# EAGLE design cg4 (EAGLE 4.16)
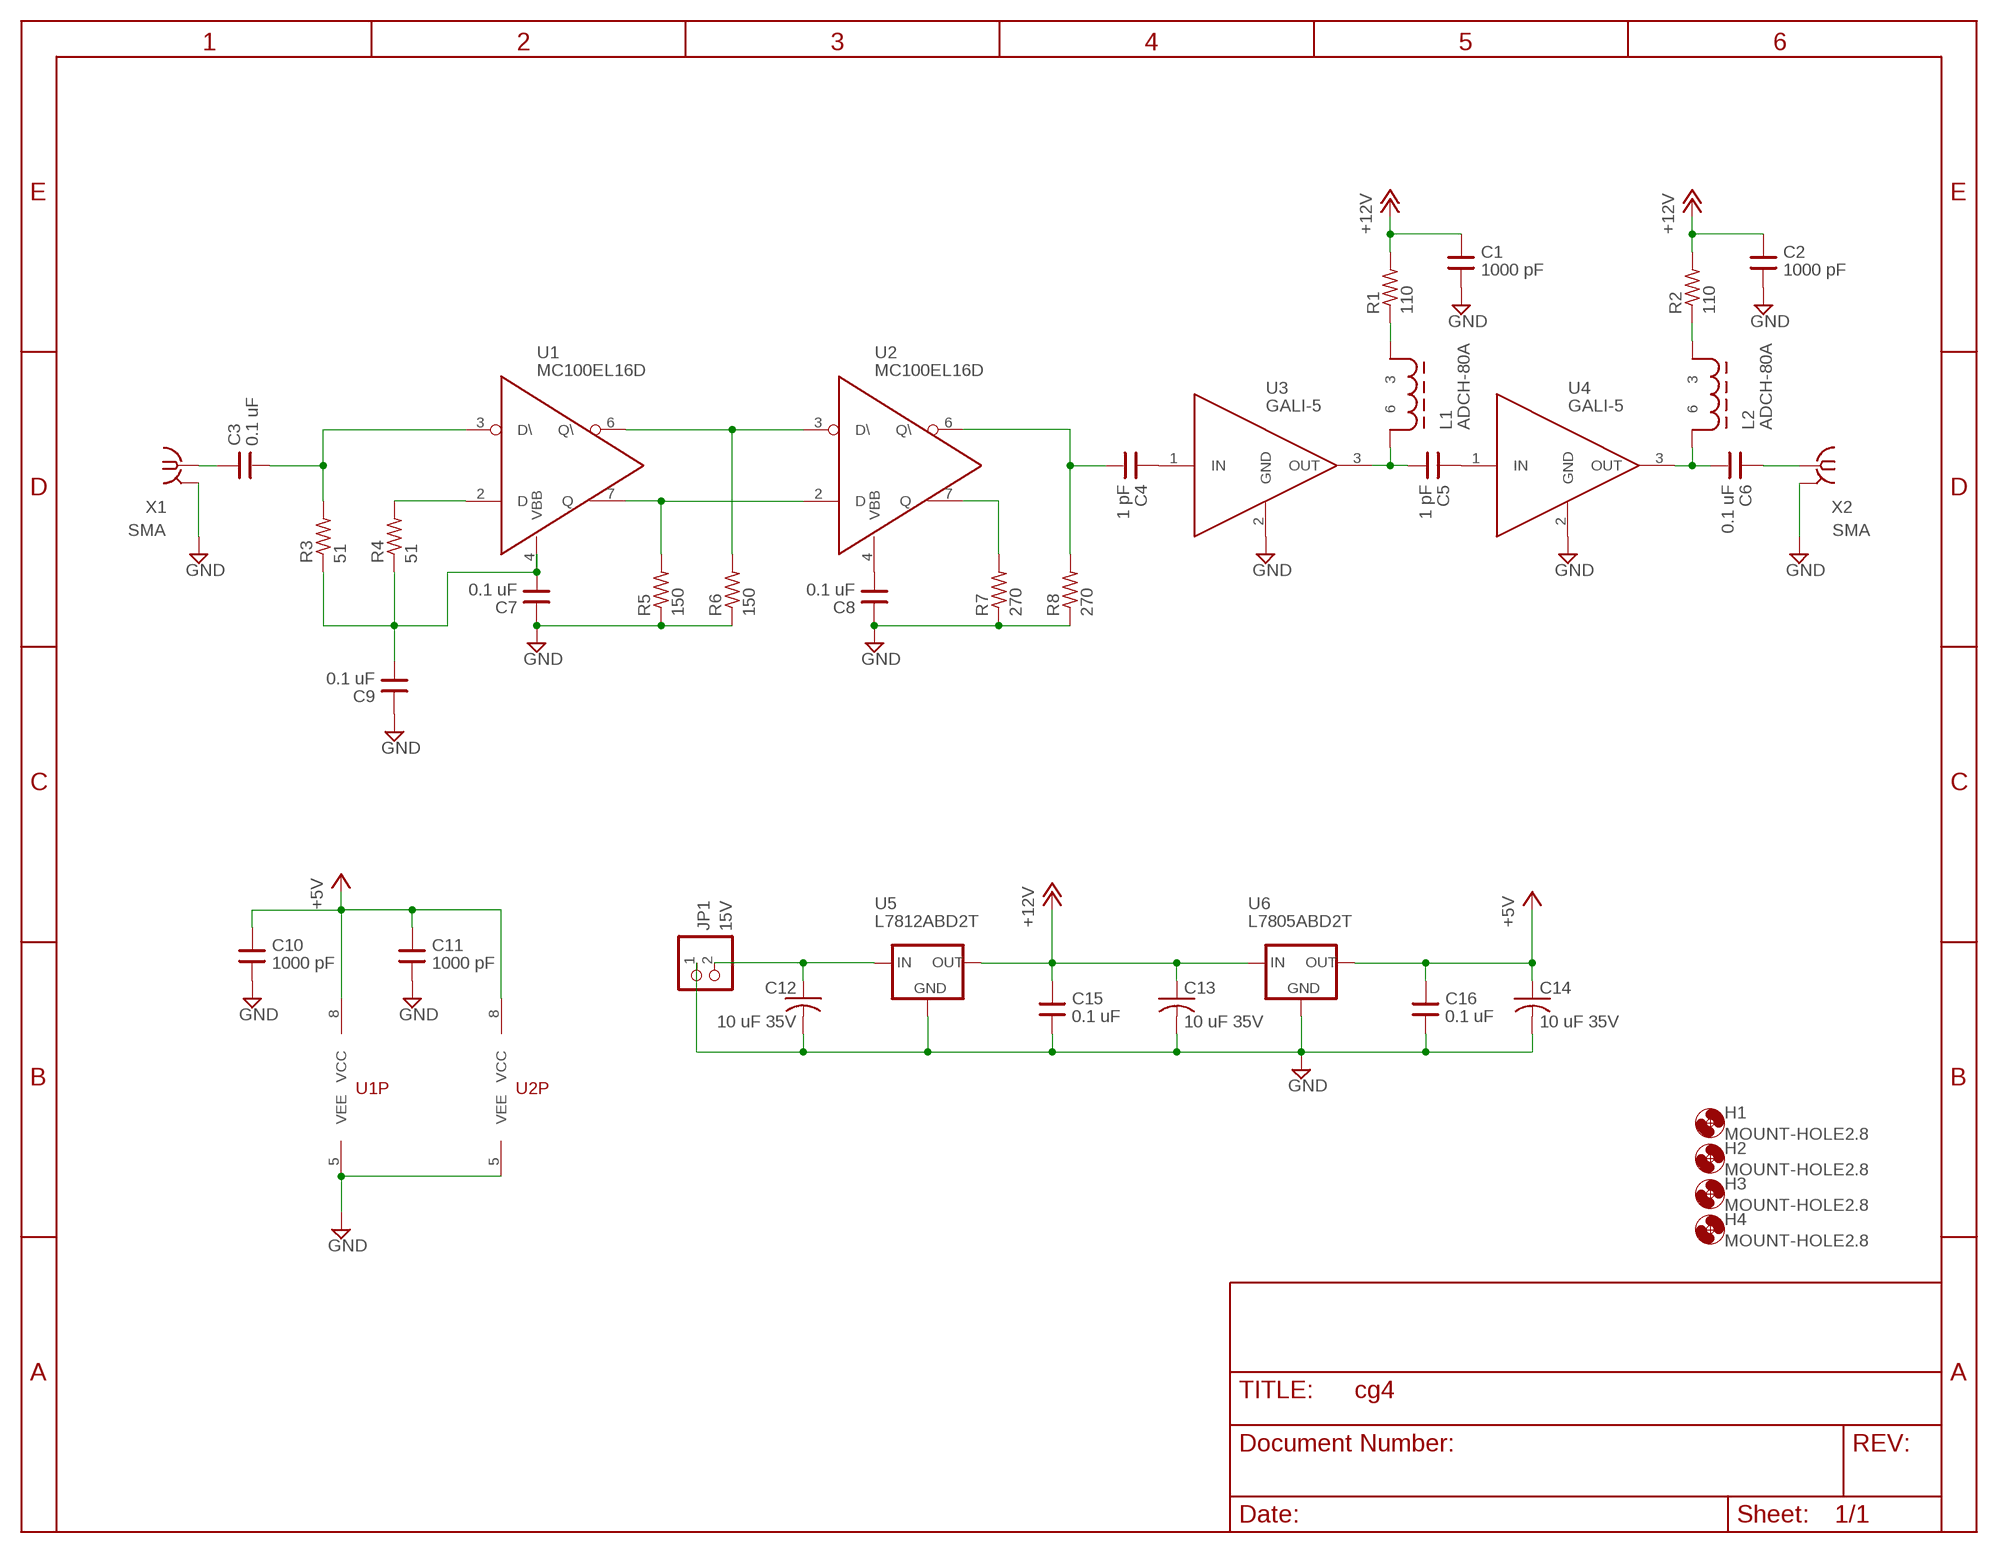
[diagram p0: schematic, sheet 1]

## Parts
C1  1000 pF  C1206  [C1206]
C2  1000 pF  C1206  [C1206]
C3  0.1 uF  C1206  [C1206]
C4  1 pF  C1206  [C1206]
C5  1 pF  C1206  [C1206]
C6  0.1 uF  C1206  [C1206]
C7  0.1 uF  C1206  [C1206]
C8  0.1 uF  C1206  [C1206]
C9  0.1 uF  C1206  [C1206]
C10  1000 pF  C1206  [C1206]
C11  1000 pF  C1206  [C1206]
C12  10 uF 35V  AVX_TAJ_CAP  [SMC-D]
C13  10 uF 35V  AVX_TAJ_CAP  [SMC-D]
C14  10 uF 35V  AVX_TAJ_CAP  [SMC-D]
C15  0.1 uF  C1206  [C1206]
C16  0.1 uF  C1206  [C1206]
H1  MOUNT-HOLE2.8  [2,8]
H2  MOUNT-HOLE2.8  [2,8]
H3  MOUNT-HOLE2.8  [2,8]
H4  MOUNT-HOLE2.8  [2,8]
JP1  15V  PINHD-1X2  [1X02]
L1  ADCH-80A  ADCH  [CD542]
L2  ADCH-80A  ADCH  [CD542]
R1  110  R-US_R2512  [R2512]
R2  110  R-US_R2512  [R2512]
R3  51  R-US_R1206  [R1206]
R4  51  R-US_R1206  [R1206]
R5  150  R-US_R1206  [R1206]
R6  150  R-US_R1206  [R1206]
R7  270  R-US_R1206  [R1206]
R8  270  R-US_R1206  [R1206]
U1  MC100EL16D  [SOIC8]
U2  MC100EL16D  [SOIC8]
U3  GALI-5  GALI  [DF782]
U4  GALI-5  GALI  [DF782]
U5  L7812ABD2T  L78XXABD2T  [D2PACK]
U6  L7805ABD2T  L78XXABD2T  [D2PACK]
X1  SMA  BU-SMA-V  [BU-SMA-V]
X2  SMA  BU-SMA-V  [BU-SMA-V]

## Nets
+5V: C10.1 C11.1 C14.+ C16.1 U1.8(VCC) U2.8(VCC) U6.3(OUT)
+12V: C1.1 C2.1 C13.+ C15.1 R1.2 R2.2 U5.3(OUT) U6.1(IN)
GND: C1.2 C2.2 C7.1 C8.1 C9.1 C10.2 C11.2 C12.- C13.- C14.- C15.2 C16.2 JP1.1 R5.1 R6.1 R7.1 R8.1 U1.5(VEE) U2.5(VEE) U3.2(GND) U4.2(GND) U5.2(GND) U6.2(GND) X1.2(GND) X2.2(GND)
N$1: C3.2 R3.2 U1.3(D\)
N$2: C4.2 R8.2 U2.6(Q\)
N$3: R4.2 U1.2(D)
N$4: C4.1 U3.1(IN)
N$5: C12.+ JP1.2 U5.1(IN)
N$6: C5.1 U4.1(IN)
N$7: R5.2 U1.7(Q) U2.2(D)
N$8: C5.2 L1.6 U3.3(OUT)
N$9: L1.3 R1.1
N$10: R6.2 U1.6(Q\) U2.3(D\)
N$11: R7.2 U2.7(Q)
N$12: C8.2 U2.4(VBB)
N$13: L2.3 R2.1
N$14: C6.2 L2.6 U4.3(OUT)
N$15: C3.1 X1.1
N$16: C6.1 X2.1
N$17: C7.2 C9.2 R3.1 R4.1 U1.4(VBB)

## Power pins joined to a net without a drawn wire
GND: U3.TAB(GND) U4.TAB(GND) X1.3(GND) X1.4(GND) X1.5(GND) X2.3(GND) X2.4(GND) X2.5(GND)

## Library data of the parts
C1-C11 C15 C16 = KE5FX:C1206
C12-C14 = KE5FX:AVX_TAJ_CAP
H1-H4 = holes:MOUNT-HOLE: MOUNTING HOLE with drill center marker
JP1 = pinhead:PINHD-1X2: PIN HEADER
L1 L2 = KE5FX:ADCH*
R1-R8 = rcl:R-US_: RESISTOR, American symbol
U1 U2 = KE5FX:MC100EL16D
U3 U4 = KE5FX:GALI*
U5 U6 = KE5FX:L78XXABD2T
X1 X2 = con-coax:BU-SMA-V: FEMALE SMA CONNECTOR Radiall distributor RS 112-3794

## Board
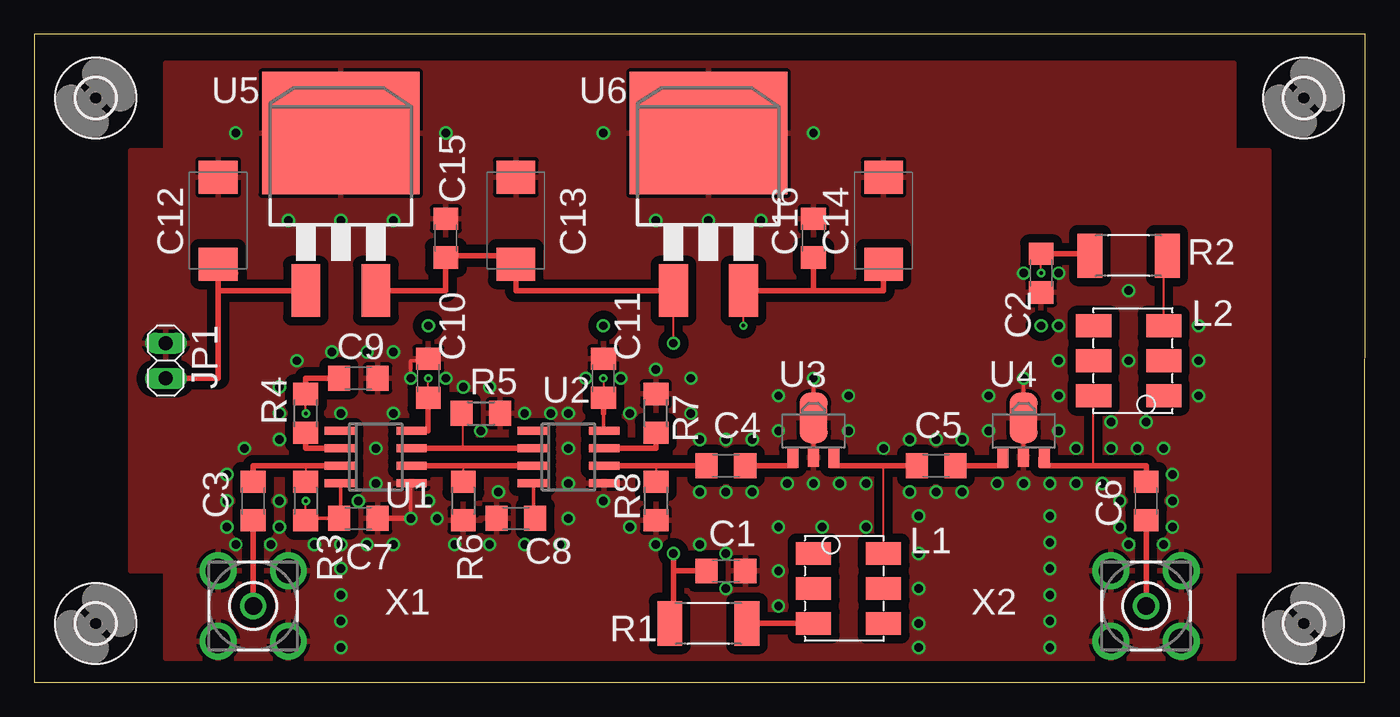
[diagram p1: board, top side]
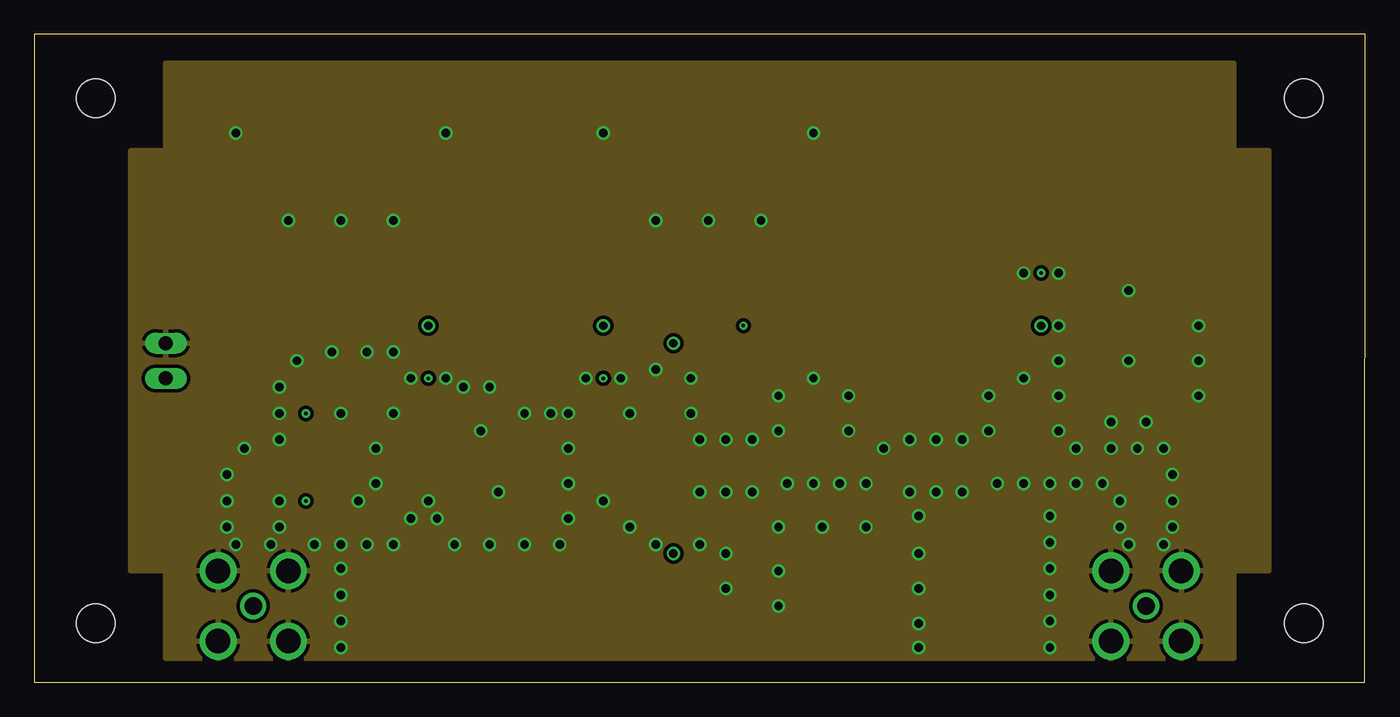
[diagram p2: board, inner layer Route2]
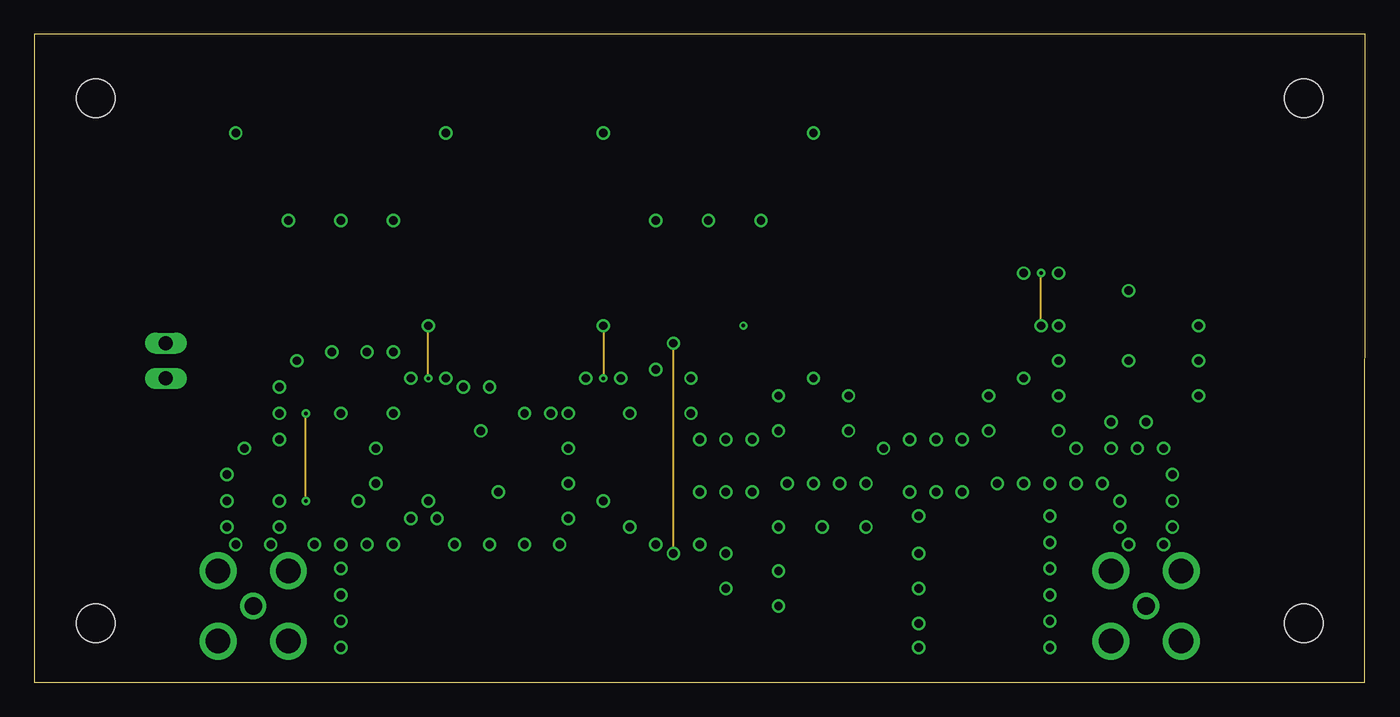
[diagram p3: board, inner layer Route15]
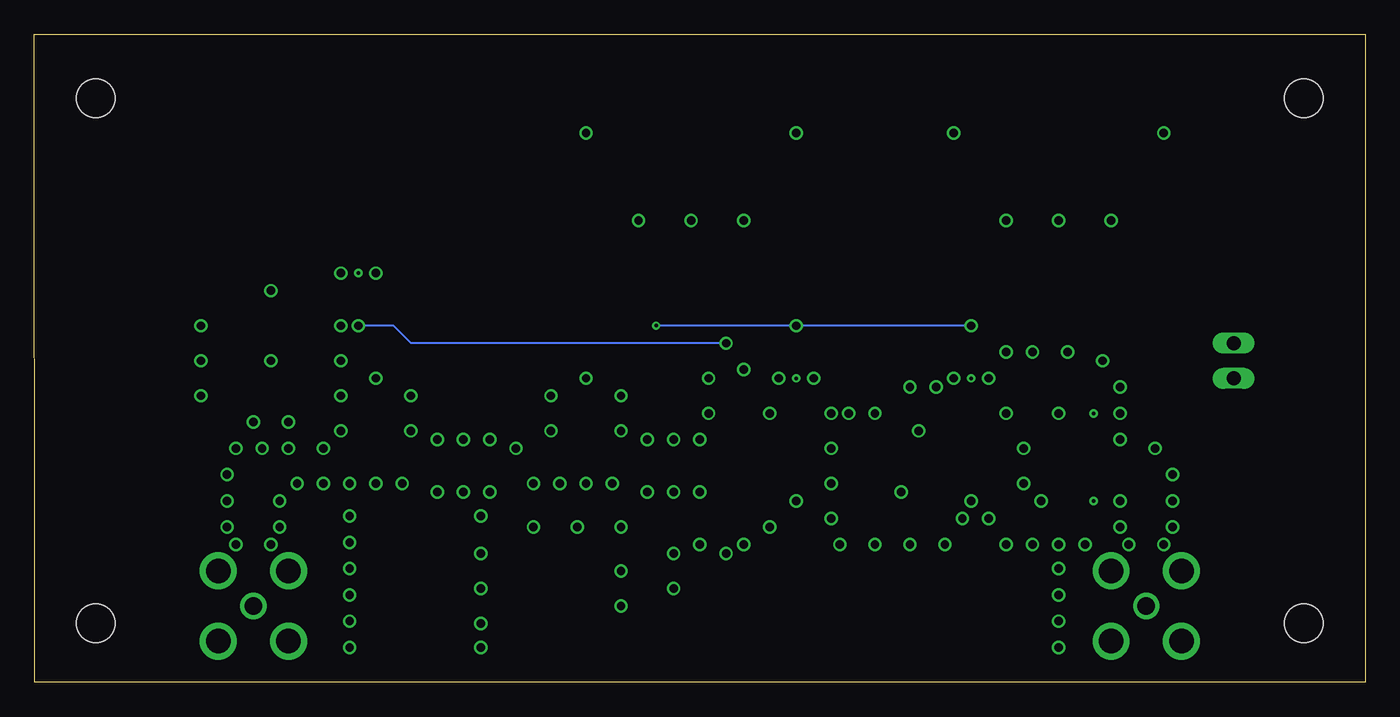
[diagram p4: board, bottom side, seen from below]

Size 96.52 x 46.99 mm. Coordinates in mm from the lower left corner, seen from the top.
Outline: 0,0 96.5,0 96.52,46.99 0,46.99 0,0
Copper layers (1+2*15+16): Top 0.035mm / dielectric 0.226mm / Route2 0.035mm / dielectric 1mm / Route15 0.035mm / dielectric 0.221mm / Bottom 0.035mm
Design rules "4pcb_4layer_8mm_clearance": minimum track width 5mil, minimum drill 0.2mm, track to track 8mil, track to pad 6mil, pad to pad 8mil, via to via 8mil, smd to smd 8mil, copper to edge 20mil, drill to drill 12mil, minimum pad ring 8mil, minimum via ring 7mil, stop-mask expansion 0mil, vias tented up to drill 0.3mm, thermal gap 10mil

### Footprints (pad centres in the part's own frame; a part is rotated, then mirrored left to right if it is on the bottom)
C1206 = smd 1.6 x 1.8: 1 -1.4,0; 2 1.4,0
SMC-D = smd 2.4 x 2.8: + -3.15,0; - 3.15,0
2,8 = hole 2.8: 0,0
1X02 = drill 1.016 long: 1 -1.27,0; 2 1.27,0
CD542 = smd 1.651 x 2.54: 1 -2.54,-2.54; 2 0,-2.54; 3 2.54,-2.54; 4 2.54,2.54; 5 0,2.54; 6 -2.54,2.54
R2512 = smd 1.8 x 3.2: 1 -2.8,0; 2 2.8,0
R1206 = smd 1.6 x 1.8: 1 -1.4,0; 2 1.4,0
SOIC8 = smd 0.6 x 2.2: 1 1.27,-0.06; 2 2.54,-0.06; 3 3.81,-0.06; 4 5.08,-0.06; 5 5.08,5.14; 6 3.81,5.14; 7 2.54,5.14; 8 1.27,5.14
DF782 = smd 0.8 x 1.4: 1 -1.499,-1.981; 2 0,-1.905; 3 1.499,-1.981 | smd 2.032 x 3.65: TAB 0,0.94
D2PACK = smd 2.083 x 3.81: 1 -2.54,-8.89; 3 2.54,-8.89 | smd 11.43 x 8.89: 2 0,2.54
BU-SMA-V = drill 1.27 round: 1 0,0 | drill 1.778 round: 2 -2.55,2.55; 3 2.55,2.55; 4 2.55,-2.55; 5 -2.55,-2.55

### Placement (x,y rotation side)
C1  50.16,8.09 0 top
C2  73.02,29.68 270 top
C3  15.87,13.17 90 top
C4  50.16,15.71 180 top
C5  65.4,15.71 180 top
C6  80.64,13.17 90 top
C7  23.49,11.9 180 top
C8  34.92,11.9 0 top
C9  23.49,22.06 180 top
C10  28.57,22.06 90 top
C11  41.27,22.06 90 top
C12  13.33,33.49 90 top
C13  34.92,33.49 90 top
C14  61.59,33.49 90 top
C15  29.84,32.22 90 top
C16  56.51,32.22 90 top
H1  92.07,42.38 0 top
H2  92.07,4.28 0 top
H3  4.44,4.28 0 top
H4  4.44,42.38 0 top
JP1  9.52,23.33 270 top
L1  59.05,6.82 270 top
L2  79.37,23.33 90 top
R1  48.89,4.28 180 top
R2  79.37,30.95 180 top
R3  19.68,13.17 90 top
R4  19.68,19.52 270 top
R5  32.38,19.52 180 top
R6  31.11,13.17 90 top
R7  45.08,19.52 270 top
R8  45.08,13.17 90 top
U1  22.22,19.52 270 top
U2  36.19,19.52 270 top
U3  56.51,18.25 0 top
U4  71.75,18.25 0 top
U5  22.22,37.3 0 top
U6  48.89,37.3 0 top
X1  15.87,5.55 0 top
X2  80.64,5.55 0 top

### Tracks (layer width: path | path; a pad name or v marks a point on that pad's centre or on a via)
+5V  (via drill 0.25 pad 0.41, 0.61 pad 0.97)
  Top 0.127: v41.27,22.06 C11.1 | 28.57,20.79 v28.57,22.06 | v51.43,25.87 U6.3
  Top 0.254: 41.27,19.52 41.27,18.25 U2.8
  Top 0.406: C11.1 41.27,19.52 | 27.3,18.25 U1.8 28.57,18.25 C10.1 28.57,20.79 | U6.3 56.51,28.41 | 56.51,30.95 C16.1 56.51,28.41 | 56.51,28.41 61.59,28.41 C14.+ 61.59,30.95
  Route15 0.127: v41.27,25.87 v41.27,22.06 | v28.57,22.06 v28.57,25.87
  Bottom 0.127: v51.43,25.87 v41.27,25.87 v28.57,25.87
+12V  (via drill 0.25 pad 0.41, 0.61, 0.61 pad 0.97)
  Top 0.127: R2.2 76.83,30.95 76.83,31.08 | v46.35,24.6 U6.1 | R1.2 46.35,5.55 | C13.+ 33.65,30.95 | v73.02,29.68 C2.1 | 48.89,8.09 C1.1
  Top 0.381: C2.1 76.83,31.08 | 46.35,5.55 46.35,8.09 | 46.35,8.09 v46.35,9.36 | 46.35,8.09 48.89,8.09
  Top 0.406: R1.2 46.35,4.28 | 45.08,28.41 U6.1 34.92,28.41 C13.+ 34.92,30.95 33.65,30.95 29.84,30.95 C15.1 29.84,28.41 U5.3
  Route15 0.127: v46.35,9.36 v46.35,24.6 | v73.02,25.87 v73.02,29.68
  Bottom 0.127: v46.35,24.6 69.21,24.6 70.48,25.87 v73.02,25.87
GND  (via drill 0.61, 0.61 pad 0.97)
  Top 0.254: C7.1 24.76,11.9 | R7.1 45.08,20.79 | v27.3,11.9 27.3,14.44 U1.5 | v56.51,22.06 U3.TAB U3.2 | v71.75,22.06 U4.TAB U4.2 | C11.2 41.27,23.33 | C9.1 24.76,22.06 | v27.3,22.06 27.3,23.33 28.57,23.33 C10.2
  Top 0.406: 24.76,11.9 v27.3,11.9 | C1.2 51.43,8.09
  other vias: 45.08,22.7 52.7,33.49 35.55,19.52 71.75,14.44 75.56,16.98 69.21,20.79 74.29,20.79 56.51,14.44 59.05,18.25 53.97,20.79 59.05,20.79 53.97,18.25 69.21,18.25 74.29,18.25 65.4,17.61 63.49,17.61 50.16,17.61 48.25,17.61 78.1,18.88 78.1,16.98 75.56,14.44 73.66,14.44 69.84,14.44 67.3,13.8 65.4,13.8 63.49,13.8 60.32,14.44 48.25,9.99 60.32,11.27 48.25,13.8 54.6,14.44 58.41,14.44 74.29,23.33 74.29,25.87 84.45,25.87 84.45,23.33 84.45,20.79 79.37,23.33 64.13,9.36 64.13,6.82 64.13,4.28 53.97,8.09 53.97,5.55 28.57,13.17 26.03,19.52 17.77,17.61 15.23,16.98 17.77,19.52 17.77,21.43 19.05,23.33 21.59,23.96 24.12,23.96 26.03,23.96 17.77,11.27 20.32,9.99 24.12,9.99 26.03,9.99 29.21,11.9 29.84,22.06 37.46,19.52 47.62,22.06 14.6,39.84 29.84,39.84 41.27,39.84 56.51,39.84 18.41,33.49 45.08,33.49 22.22,33.49 48.89,33.49 38.73,16.98 38.73,14.44 38.73,11.9 43.17,11.27 57.14,11.27 33.01,9.99 30.48,9.99 38.09,9.99 45.08,9.99 31.11,21.43 24.76,16.98 24.76,14.44 22.22,19.52 23.49,13.17 38.73,19.52 33.01,21.43 32.38,18.25 43.17,19.52 33.65,13.8 41.27,13.17 50.16,9.36 26.03,33.49 40,22.06 42.54,22.06 71.75,29.68 74.29,29.68 50.16,6.82 17.77,13.17 17.14,9.99 14.6,9.99 13.96,11.27 13.96,13.17 22.22,9.99 13.96,15.07 35.55,9.99 47.62,19.52 77.47,14.44 78.73,13.17 82.55,13.17 82.55,11.27 81.91,9.99 79.37,9.99 78.73,11.27 82.55,15.07 81.91,16.98 80.64,18.88 80,16.98 67.3,17.61 61.59,16.98 52.06,17.61 52.06,13.8 50.16,13.8 53.97,11.27 79.37,28.41 22.22,2.54 22.22,4.45 22.22,6.35 22.22,8.26 73.66,2.54 73.66,4.45 73.66,6.35 73.66,8.26 73.66,10.16 73.66,12.07 64.13,12.07 64.13,2.54
  pour Route2 (isolate 0.254): 6.98,38.57 6.98,8.09 9.52,8.09 9.52,1.74 86.99,1.74 86.99,8.09 89.53,8.09 89.53,38.57 86.99,38.57 86.99,44.92 9.52,44.92 9.52,38.57
  pour Top (isolate 0.61): 6.98,38.57 6.98,8.09 9.52,8.09 9.52,1.74 86.99,1.74 86.99,8.09 89.53,8.09 89.53,38.57 86.99,38.57 86.99,44.92 9.52,44.92 9.52,38.57
N$1
  Top 0.127: U1.3 20.95,15.71 19.68,15.71 R3.2
  Top 0.381: 20.95,15.71 15.87,15.71 C3.2
  Top 0.406: U1.3 22.22,15.71 | C3.2 15.87,14.44
N$2
  Top 0.127: 45.08,15.71 R8.2
  Top 0.254: 42.54,15.71 U2.6 41.27,15.71
  Top 0.381: C4.2 45.08,15.71 42.54,15.71
  Top 0.406: R8.2 45.08,14.44 | C4.2 48.89,15.71
N$3
  Top 0.381: 19.68,16.98 U1.2
  Top 0.406: U1.2 22.22,16.98 | 19.68,18.25 R4.2 19.68,16.98
N$4
  Top 0.127: 55.24,15.71 U3.1
  Top 0.381: C4.1 55.24,15.71
N$5
  Top 0.127: C12.+ 12.06,29.68
  Top 0.254: C12.+ 14.6,29.68
  Top 0.406: JP1.2 13.33,22.06 13.33,28.41 | 13.33,28.41 C12.+ 13.33,30.95 | 14.6,29.68 13.33,29.68 13.33,28.41 | 13.33,28.41 U5.1
N$6
  Top 0.254: C5.1 66.67,15.71 | 70.48,15.71 U4.1
  Top 0.381: C5.1 70.48,15.71
N$7
  Top 0.127: 31.11,16.98 31.11,19.52
  Top 0.254: U1.7 27.3,16.98
  Top 0.305: 31.11,19.52 R5.2
  Top 0.381: U1.7 31.11,16.98 36.19,16.98
  Top 0.406: 36.19,16.98 U2.2
N$8
  Top 0.127: L1.6 61.59,15.71
  Top 0.254: 57.78,15.71 U3.3
  Top 0.381: C5.2 61.59,15.71 57.78,15.71
  Top 0.406: C5.2 64.13,15.71
N$9
  Top 0.254: R1.1 51.43,5.55
  Top 0.406: L1.3 51.43,4.28 51.43,5.55
N$10
  Top 0.127: 31.11,15.71 R6.2
  Top 0.254: U1.6 27.3,15.71 | R6.2 31.11,14.44
  Top 0.381: U1.6 31.11,15.71 U2.3
  Top 0.406: U2.3 36.19,15.71
N$11
  Top 0.254: U2.7 41.27,16.98
  Top 0.381: U2.7 45.08,16.98 R7.2
  Top 0.406: R7.2 45.08,18.25
N$12
  Top 0.254: 36.19,14.44 36.19,11.9 C8.2
  Top 0.406: 36.19,14.44 U2.4
N$13
  Top 0.127: L2.3 81.91,29.68 R2.1
N$14
  Top 0.127: 76.83,15.71 L2.6
  Top 0.381: 73.02,15.71 76.83,15.71 80.64,15.71
  Top 0.406: 80.64,14.44 C6.2 80.64,15.71 | U4.3 73.02,16.27 73.02,15.71
N$15
  Top 0.381: X1.1 C3.1
N$16
  Top 0.381: X2.1 C6.1
N$17  (via drill 0.25 pad 0.41)
  Top 0.127: v19.68,19.52 19.68,20.79 | 19.68,11.9 v19.68,13.17
  Top 0.254: U1.4 22.22,14.44 22.22,11.9 C7.2 19.68,11.9 R3.1
  Top 0.406: 19.68,20.79 R4.1 19.68,22.06 C9.2
  Route15 0.127: v19.68,13.17 v19.68,19.52

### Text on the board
tDocu: VHF-Microwave | Comb Generator | 8/07 KE5FX | +15V | RF In | RF Out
